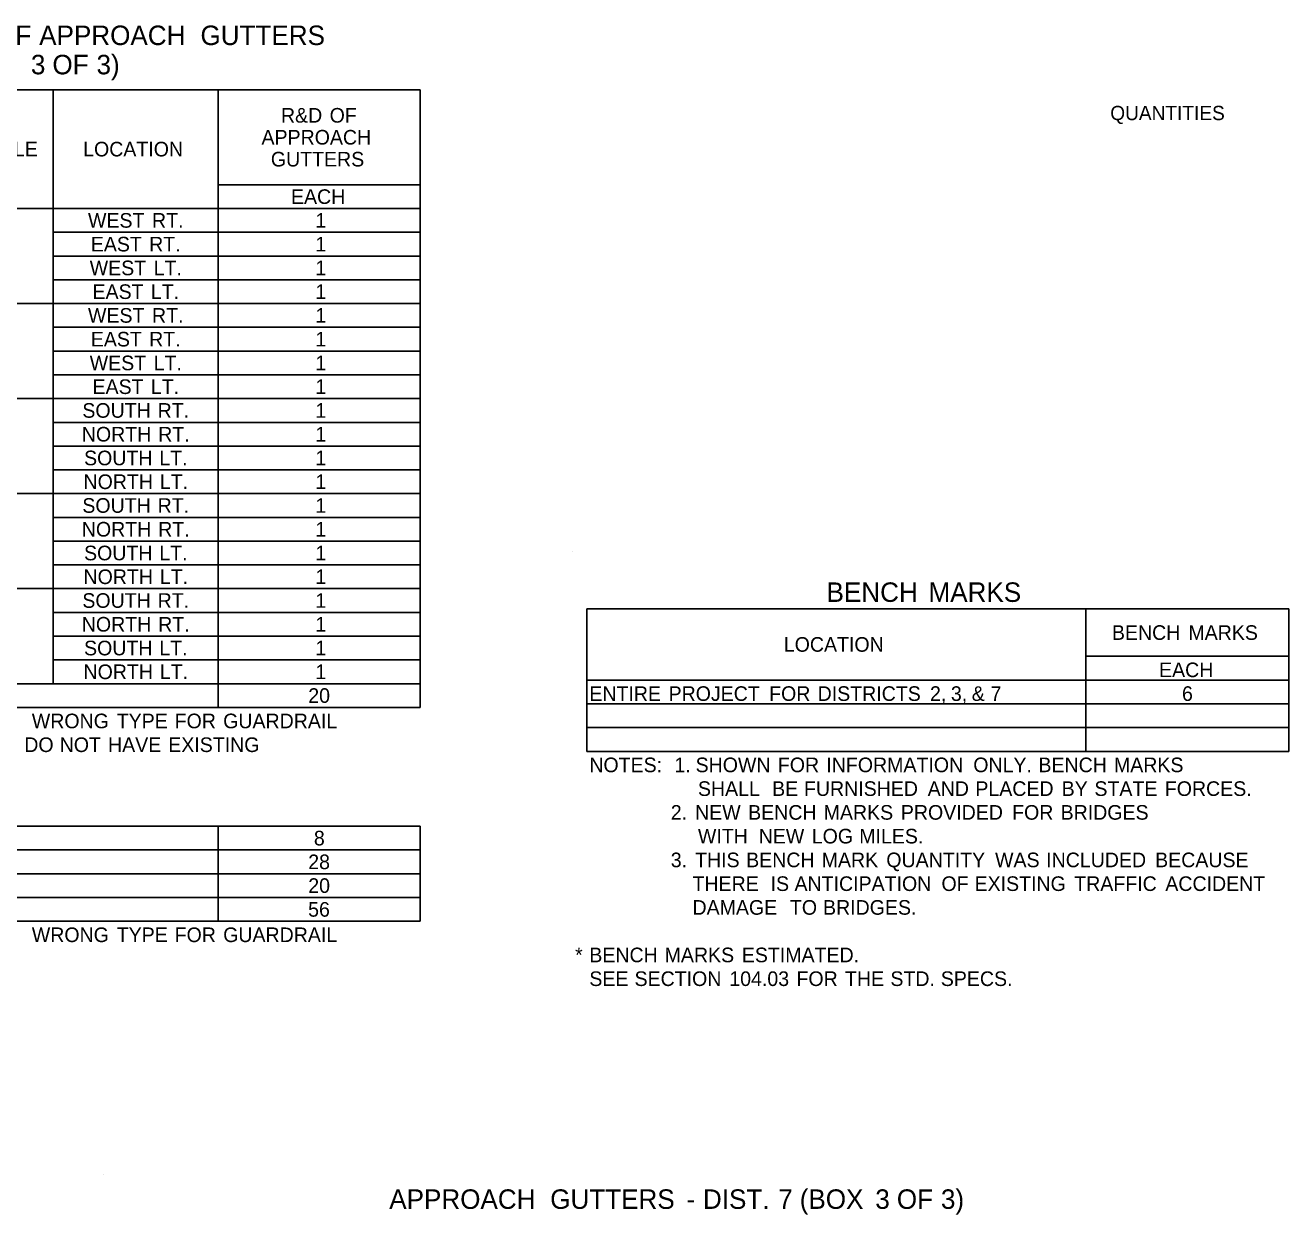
# Model space of a CAD drawing. Extents: x 544250 to 1930787, y -1948365 to 596640.
# Drawn here: x 554718 to 555236, y -1947813 to -1947325 of the extents above; entities that cross this region are included whole.
import ezdxf

# ---------------------------------------------------------------- set-up
doc = ezdxf.new("R2010")
doc.units = 0
doc.layers.add('Default', color=7, linetype='Continuous')
doc.layers.add('R_Border Prem', color=7, linetype='Continuous')

msp = doc.modelspace()

# ---------------------------------------------------------------- linework, layer by layer
at = {"layer": 'Default'}
for p, q in [((554522.96, -1947351.42), (554879.81, -1947351.42)), ((554729.18, -1947595.17), (554729.18, -1947351.42)), ((554796.94, -1947604.92), (554796.94, -1947351.42)), ((554879.81, -1947604.92), (554879.81, -1947351.42)), ((554879.81, -1947604.92), (554879.81, -1947351.42)), ((554796.94, -1947390.42), (554879.81, -1947390.42)), ((554796.94, -1947390.42), (554879.81, -1947390.42)), ((554522.96, -1947400.17), (554879.81, -1947400.17)), ((554729.18, -1947409.92), (554879.81, -1947409.92)), ((554729.18, -1947419.67), (554879.81, -1947419.67)), ((554729.18, -1947429.42), (554879.81, -1947429.42)), ((554522.96, -1947439.17), (554879.81, -1947439.17)), ((554729.18, -1947448.92), (554879.81, -1947448.92)), ((554729.18, -1947458.67), (554879.81, -1947458.67)), ((554729.18, -1947468.42), (554879.81, -1947468.42)), ((554522.96, -1947478.17), (554879.81, -1947478.17)), ((554729.18, -1947487.92), (554879.81, -1947487.92)), ((554729.18, -1947497.67), (554879.81, -1947497.67)), ((554729.18, -1947507.42), (554879.81, -1947507.42)), ((554522.96, -1947517.17), (554879.81, -1947517.17)), ((554729.18, -1947526.92), (554879.81, -1947526.92)), ((554729.18, -1947536.67), (554879.81, -1947536.67)), ((554942.49, -1947541.04), (554942.49, -1947541.04)), ((554729.18, -1947546.42), (554879.81, -1947546.42)), ((554522.96, -1947556.17), (554879.81, -1947556.17)), ((554948.34, -1947564.44), (555236.45, -1947564.44)), ((554948.34, -1947622.94), (554948.34, -1947564.44)), ((554948.34, -1947622.94), (554948.34, -1947564.44)), ((555153.09, -1947622.94), (555153.09, -1947564.44)), ((555236.45, -1947583.94), (555236.45, -1947564.44)), ((554729.18, -1947565.92), (554879.81, -1947565.92)), ((554729.18, -1947575.67), (554879.81, -1947575.67)), ((554729.18, -1947585.42), (554879.81, -1947585.42)), ((555153.09, -1947583.94), (555236.45, -1947583.94)), ((555236.45, -1947622.94), (555236.45, -1947583.94)), ((554522.96, -1947595.17), (554879.81, -1947595.17)), ((554948.34, -1947593.69), (555236.45, -1947593.69)), ((555153.09, -1947622.94), (555153.09, -1947593.69)), ((554522.96, -1947604.92), (554879.81, -1947604.92)), ((554948.34, -1947603.44), (555236.45, -1947603.44)), ((554948.34, -1947613.19), (555236.45, -1947613.19)), ((554948.34, -1947622.94), (555236.45, -1947622.94)), ((554522.96, -1947653.67), (554879.81, -1947653.67)), ((554522.96, -1947653.67), (554879.81, -1947653.67)), ((554796.94, -1947692.67), (554796.94, -1947653.67)), ((554879.81, -1947692.67), (554879.81, -1947653.67)), ((554879.81, -1947692.67), (554879.81, -1947653.67)), ((554522.96, -1947663.42), (554879.81, -1947663.42)), ((554522.96, -1947673.17), (554879.81, -1947673.17)), ((554522.96, -1947682.92), (554879.81, -1947682.92)), ((554522.96, -1947692.67), (554879.81, -1947692.67)), ((554749.69, -1947796.7), (554749.69, -1947796.7))]:
    msp.add_line(p, q, dxfattribs=at)

# ---------------------------------------------------------------- texts
for s, height, p in [(' OF', 8, (554702.36, -1947333.09)), (' APPROACH', 8, (554720.47, -1947333.09)), (' GUTTERS', 8, (554786.69, -1947333.09)), (' 3', 8, (554717.07, -1947345.09)), (' OF', 8, (554725.9, -1947345.09)), (' 3)', 8, (554744.01, -1947345.09)), ('R&D', 6, (554822.71, -1947364.92)), (' OF', 6, (554840.46, -1947364.92)), ('APPROACH', 6, (554814.71, -1947373.92)), (' MILE', 6, (554701.93, -1947378.79)), ('LOCATION', 6, (554741.5, -1947378.79)), ('GUTTERS', 6, (554818.55, -1947382.92)), ('EACH', 6, (554826.82, -1947398.29)), ('WEST', 6, (554743.48, -1947408.04)), (' RT.', 6, (554767.53, -1947408.04)), ('1', 6, (554836.82, -1947408.04)), ('EAST', 6, (554744.64, -1947417.79)), (' RT.', 6, (554766.37, -1947417.79)), ('1', 6, (554836.82, -1947417.79)), ('WEST', 6, (554744.18, -1947427.54)), (' LT.', 6, (554768.23, -1947427.54)), ('1', 6, (554836.82, -1947427.54)), ('EAST', 6, (554745.34, -1947437.29)), (' LT.', 6, (554767.07, -1947437.29)), ('1', 6, (554836.82, -1947437.29)), ('WEST', 6, (554743.48, -1947447.04)), (' RT.', 6, (554767.53, -1947447.04)), ('1', 6, (554836.82, -1947447.04)), ('EAST', 6, (554744.64, -1947456.79)), (' RT.', 6, (554766.37, -1947456.79)), ('1', 6, (554836.82, -1947456.79)), ('WEST', 6, (554744.18, -1947466.54)), (' LT.', 6, (554768.23, -1947466.54)), ('1', 6, (554836.82, -1947466.54)), ('EAST', 6, (554745.34, -1947476.29)), (' LT.', 6, (554767.07, -1947476.29)), ('1', 6, (554836.82, -1947476.29)), ('SOUTH', 6, (554741.17, -1947486.04)), (' RT.', 6, (554769.84, -1947486.04)), ('1', 6, (554836.82, -1947486.04)), ('NORTH', 6, (554740.94, -1947495.79)), (' RT.', 6, (554770.07, -1947495.79)), ('1', 6, (554836.82, -1947495.79)), ('SOUTH', 6, (554741.87, -1947505.54)), (' LT.', 6, (554770.54, -1947505.54)), ('1', 6, (554836.82, -1947505.54)), ('NORTH', 6, (554741.64, -1947515.29)), (' LT.', 6, (554770.77, -1947515.29)), ('1', 6, (554836.82, -1947515.29)), ('SOUTH', 6, (554741.17, -1947525.04)), (' RT.', 6, (554769.84, -1947525.04)), ('1', 6, (554836.82, -1947525.04)), ('NORTH', 6, (554740.94, -1947534.79)), (' RT.', 6, (554770.07, -1947534.79)), ('1', 6, (554836.82, -1947534.79)), ('SOUTH', 6, (554741.87, -1947544.54)), (' LT.', 6, (554770.54, -1947544.54)), ('1', 6, (554836.82, -1947544.54)), ('NORTH', 6, (554741.64, -1947554.29)), (' LT.', 6, (554770.77, -1947554.29)), ('1', 6, (554836.82, -1947554.29)), ('BENCH', 8, (555046.7, -1947561.61)), (' MARKS', 8, (555085.59, -1947561.61)), ('SOUTH', 6, (554741.17, -1947564.04)), (' RT.', 6, (554769.84, -1947564.04)), ('1', 6, (554836.82, -1947564.04)), ('NORTH', 6, (554740.94, -1947573.79)), (' RT.', 6, (554770.07, -1947573.79)), ('1', 6, (554836.82, -1947573.79)), ('BENCH', 6, (555163.86, -1947577.19)), (' MARKS', 6, (555193.03, -1947577.19)), ('SOUTH', 6, (554741.87, -1947583.54)), (' LT.', 6, (554770.54, -1947583.54)), ('1', 6, (554836.82, -1947583.54)), ('LOCATION', 6, (555029.16, -1947582.06)), ('NORTH', 6, (554741.64, -1947593.29)), (' LT.', 6, (554770.77, -1947593.29)), ('1', 6, (554836.82, -1947593.29)), ('EACH', 6, (555183.21, -1947592.49)), ('ENTIRE', 6, (554949.31, -1947602.24)), (' PROJECT', 6, (554979.61, -1947602.24)), (' FOR', 6, (555020.9, -1947602.24)), (' DISTRICTS', 6, (555040.81, -1947602.24)), (' 2,', 6, (555086.95, -1947602.24)), (' 3,', 6, (555095.52, -1947602.24)), (' &', 6, (555104.09, -1947602.24)), (' 7', 6, (555111.82, -1947602.24)), ('6', 6, (555192.63, -1947602.24)), ('20', 6, (554833.92, -1947603.04)), (' WRONG', 6, (554718.19, -1947613.47)), (' TYPE', 6, (554753.05, -1947613.47)), (' FOR', 6, (554776.83, -1947613.47)), (' GUARDRAIL', 6, (554796.75, -1947613.47)), (' DO', 6, (554715.1, -1947623.22)), (' NOT', 6, (554729.63, -1947623.22)), (' HAVE', 6, (554749.49, -1947623.22)), (' EXISTING', 6, (554774.2, -1947623.22)), ('NOTES:', 6, (554949.31, -1947631.49)), ('  1.', 6, (554979.79, -1947631.49)), (' SHOWN', 6, (554990.71, -1947631.49)), (' FOR', 6, (555024.48, -1947631.49)), (' INFORMATION', 6, (555044.39, -1947631.49)), (' ONLY.', 6, (555104.72, -1947631.49)), (' BENCH', 6, (555131.47, -1947631.49)), (' MARKS', 6, (555162.47, -1947631.49)), ('                    SHALL', 6, (554949.31, -1947641.24)), (' BE', 6, (555022.13, -1947641.24)), (' FURNISHED', 6, (555035.2, -1947641.24)), (' AND', 6, (555085.99, -1947641.24)), (' PLACED', 6, (555105.57, -1947641.24)), (' BY', 6, (555141, -1947641.24)), (' STATE', 6, (555154.45, -1947641.24)), (' FORCES.', 6, (555183.35, -1947641.24)), ('               2.', 6, (554949.31, -1947650.99)), (' NEW', 6, (554990.49, -1947650.99)), (' BENCH', 6, (555012.28, -1947650.99)), (' MARKS', 6, (555043.28, -1947650.99)), (' PROVIDED', 6, (555074.98, -1947650.99)), (' FOR', 6, (555120.66, -1947650.99)), (' BRIDGES', 6, (555140.57, -1947650.99)), ('8', 6, (554836.23, -1947661.54)), ('                    WITH', 6, (554949.31, -1947660.74)), (' NEW', 6, (555016.61, -1947660.74)), (' LOG', 6, (555038.4, -1947660.74)), (' MILES.', 6, (555057.9, -1947660.74)), ('28', 6, (554833.9, -1947671.29)), ('               3.', 6, (554949.31, -1947670.49)), (' THIS', 6, (554990.49, -1947670.49)), (' BENCH', 6, (555011.47, -1947670.49)), (' MARK', 6, (555042.47, -1947670.49)), (' QUANTITY', 6, (555069.01, -1947670.49)), (' WAS', 6, (555113.66, -1947670.49)), (' INCLUDED', 6, (555134.65, -1947670.49)), (' BECAUSE', 6, (555179.38, -1947670.49)), ('                   THERE', 6, (554949.31, -1947680.24)), (' IS', 6, (555021.51, -1947680.24)), (' ANTICIPATION', 6, (555031.32, -1947680.24)), (' OF', 6, (555091.65, -1947680.24)), (' EXISTING', 6, (555105.24, -1947680.24)), (' TRAFFIC', 6, (555146.17, -1947680.24)), (' ACCIDENT', 6, (555183.56, -1947680.24)), ('20', 6, (554833.92, -1947681.04)), ('56', 6, (554833.86, -1947690.79)), ('                   DAMAGE', 6, (554949.31, -1947689.99)), (' TO', 6, (555029.43, -1947689.99)), (' BRIDGES.', 6, (555043.03, -1947689.99)), (' WRONG', 6, (554718.19, -1947701.22)), (' FOR', 6, (554776.83, -1947701.22)), (' GUARDRAIL', 6, (554796.75, -1947701.22)), (' TYPE', 6, (554753.05, -1947701.22)), ('*', 6, (554943.46, -1947709.49)), ('BENCH', 6, (554949.31, -1947709.49)), (' MARKS', 6, (554977.99, -1947709.49)), (' ESTIMATED.', 6, (555009.69, -1947709.49)), ('SEE', 6, (554949.31, -1947719.24)), (' SECTION', 6, (554965.64, -1947719.24)), (' 104.03', 6, (555004.55, -1947719.24)), (' FOR', 6, (555032.13, -1947719.24)), (' THE', 6, (555052.04, -1947719.24)), (' STD.', 6, (555070.69, -1947719.24)), (' SPECS.', 6, (555091.38, -1947719.24)), ('APPROACH', 8, (554867.16, -1947810.7)), (' GUTTERS', 8, (554930.27, -1947810.7)), (' DIST.', 8, (554992.99, -1947810.7)), (' 7', 8, (555023.89, -1947810.7)), (' (BOX', 8, (555032.71, -1947810.7)), (' 3', 8, (555063.75, -1947810.7)), (' OF', 8, (555072.58, -1947810.7)), (' 3)', 8, (555090.69, -1947810.7)), (' -', 8, (554986.24, -1947810.7))]:
    msp.add_text(s, height=height, dxfattribs=at).set_placement(p)
at = {"layer": 'R_Border Prem'}
msp.add_text('QUANTITIES', height=5.862, rotation=360, dxfattribs=at).set_placement((555163.17, -1947363.9))

doc.saveas('drawing.dxf')
